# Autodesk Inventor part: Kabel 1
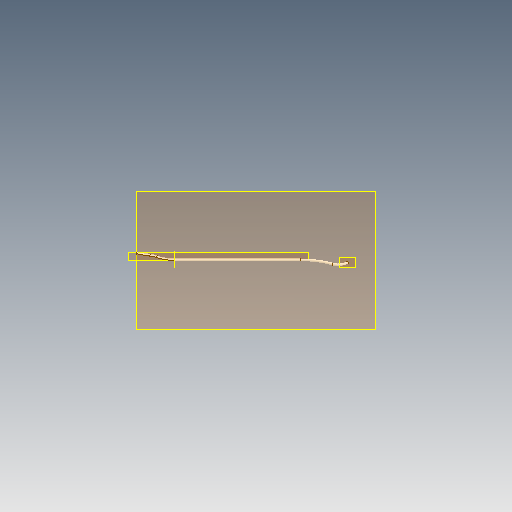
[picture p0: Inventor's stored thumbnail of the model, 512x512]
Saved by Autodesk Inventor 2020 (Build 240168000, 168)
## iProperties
Created: 2025-04
Part Number: Kabel 1
Material: Polyetylen, S vysokou hustotou
Document SubType Name: Modeling
Designer: doma
Density: 0.952 g/cm^3
Appearance: Hladká – špinavě bílá
Mass: 7.53465 g
Surface Area: 63.7104 cm^2
Volume: 7.91455 cm^3
Author: doma
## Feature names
1. Tažení1
2. Tažení2
## Parameters: d0 = 135 deg, d1 = 15 mm, d2 = 5 mm, d3 = 0, d4 = 0, d5 = 0, d6 = 0
